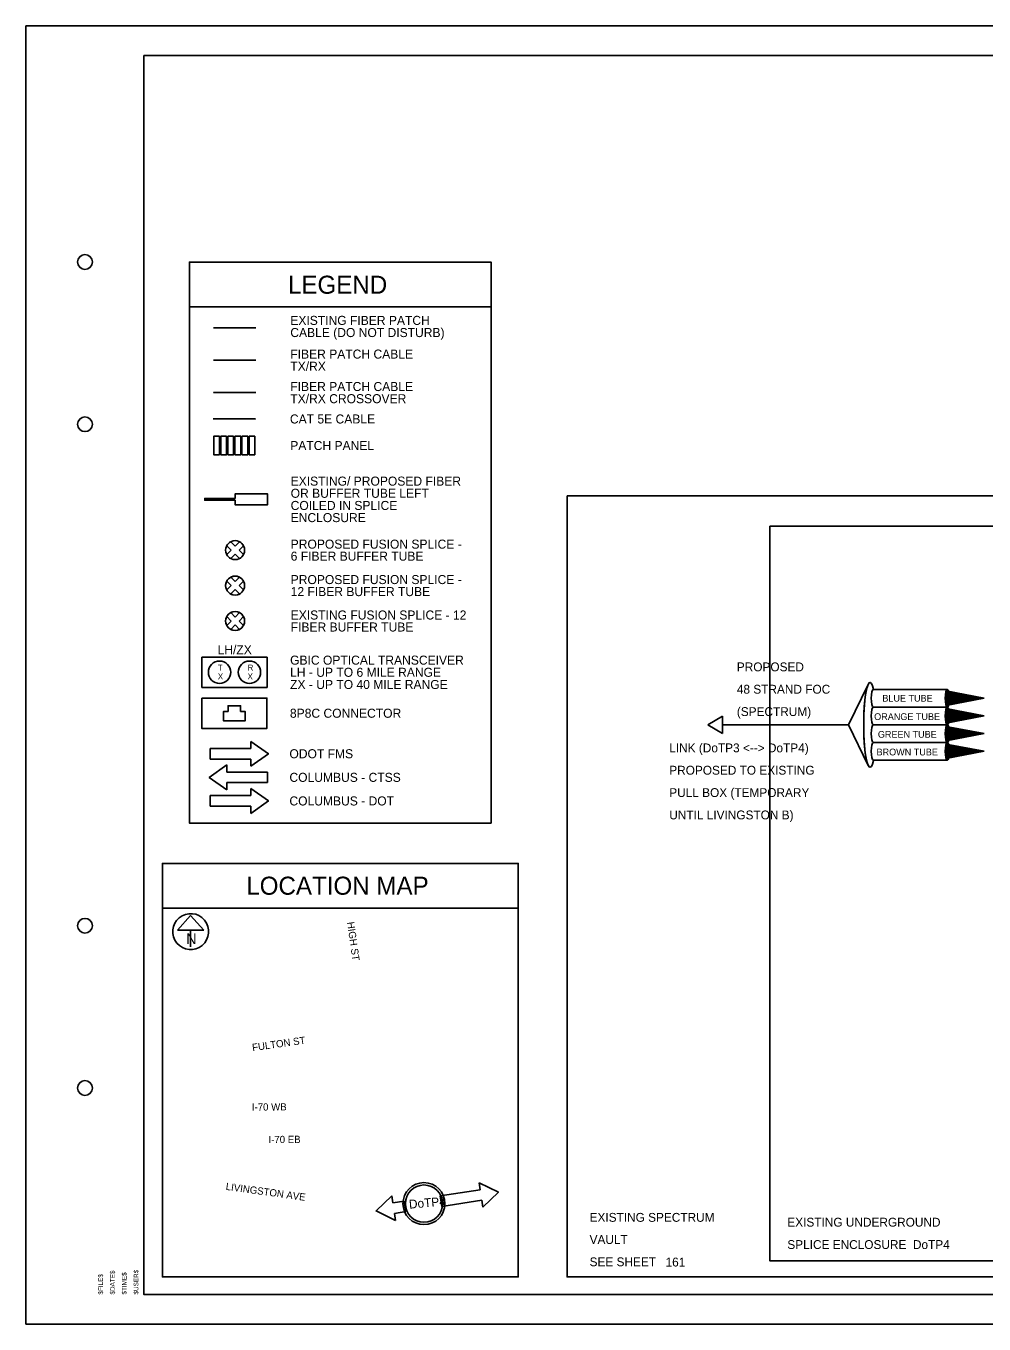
# Model space of a CAD drawing. Extents: x 1805893 to 1833564, y 708898 to 716199.
# Drawn here: x 1832883.8 to 1833208.6, y 714257.9 to 714697.9 of the extents above; entities that cross this region are included whole.
import ezdxf

# ---------------------------------------------------------------- set-up
doc = ezdxf.new("R2010")
doc.units = 0
for name, color, linetype in [('BR_P_Sub_Hidden', 7, 'Continuous'), ('BR_X_Slab_Object', 7, 'Continuous'), ('SH_Border', 7, 'Continuous'), ('SH_Cut_Line', 7, 'Continuous'), ('SH_Data', 7, 'Continuous'), ('SH_Text', 7, 'Continuous'), ('UT_X_Misc_Cells', 7, 'Continuous')]:
    doc.layers.add(name, color=color, linetype=linetype)

msp = doc.modelspace()

# ---------------------------------------------------------------- linework, layer by layer
at = {"layer": 'BR_P_Sub_Hidden'}
for points in [[(1833067.2, 714538.6), (1833508.62, 714538.6), (1833508.62, 714273.91), (1833067.2, 714273.91)], [(1833135.95, 714528.32), (1833459.05, 714528.32), (1833459.05, 714279.3), (1833135.95, 714279.3)]]:
    msp.add_lwpolyline(points, close=True, dxfattribs=at)
at = {"layer": 'SH_Border'}
msp.add_lwpolyline([(1832923.78, 714687.91), (1833553.78, 714687.91), (1833553.78, 714267.91), (1832923.78, 714267.91)], close=True, dxfattribs=at)
for centre in [(1832903.78, 714617.91), (1832903.78, 714562.91), (1832903.78, 714392.91), (1832903.78, 714337.91)]:
    msp.add_circle(centre, 2.5, dxfattribs=at)
at = {"layer": 'SH_Cut_Line'}
msp.add_lwpolyline([(1832883.78, 714257.91), (1833563.78, 714257.91), (1833563.78, 714697.91), (1832883.78, 714697.91)], close=True, dxfattribs=at)
at = {"layer": 'SH_Data'}
for p, q in [((1832947.38, 714595.63), (1832961.72, 714595.63)), ((1832947.38, 714584.63), (1832961.72, 714584.63)), ((1832953.32, 714520.23), (1832951.83, 714521.72)), ((1832951.83, 714521.72), (1832953.32, 714520.23)), ((1832954.68, 714521.58), (1832953.19, 714523.08)), ((1832954.68, 714521.58), (1832953.19, 714523.08)), ((1832954.68, 714521.58), (1832956.17, 714523.08)), ((1832956.17, 714523.08), (1832954.68, 714521.58)), ((1832956.03, 714520.23), (1832957.53, 714521.72)), ((1832956.03, 714520.23), (1832957.53, 714521.72)), ((1832951.83, 714518.74), (1832953.32, 714520.23)), ((1832953.32, 714520.23), (1832951.83, 714518.74)), ((1832953.19, 714517.38), (1832954.68, 714518.87)), ((1832953.19, 714517.38), (1832954.68, 714518.87)), ((1832956.17, 714517.38), (1832954.68, 714518.87)), ((1832954.68, 714518.87), (1832956.17, 714517.38)), ((1832957.53, 714518.74), (1832956.03, 714520.23)), ((1832957.53, 714518.74), (1832956.03, 714520.23)), ((1832953.32, 714508.22), (1832951.83, 714509.71)), ((1832953.32, 714508.22), (1832951.83, 714509.71)), ((1832951.83, 714506.73), (1832953.32, 714508.22)), ((1832951.83, 714506.73), (1832953.32, 714508.22)), ((1832954.68, 714509.57), (1832953.19, 714511.07)), ((1832953.19, 714511.07), (1832954.68, 714509.57)), ((1832954.68, 714509.57), (1832956.17, 714511.07)), ((1832954.68, 714509.57), (1832956.17, 714511.07)), ((1832956.03, 714508.22), (1832957.53, 714509.71)), ((1832957.53, 714509.71), (1832956.03, 714508.22)), ((1832957.53, 714506.73), (1832956.03, 714508.22)), ((1832956.03, 714508.22), (1832957.53, 714506.73)), ((1832953.19, 714505.37), (1832954.68, 714506.86)), ((1832954.68, 714506.86), (1832953.19, 714505.37)), ((1832956.17, 714505.37), (1832954.68, 714506.86)), ((1832956.17, 714505.37), (1832954.68, 714506.86)), ((1832954.68, 714497.57), (1832953.19, 714499.06)), ((1832953.19, 714499.06), (1832954.68, 714497.57)), ((1832954.68, 714497.57), (1832956.17, 714499.06)), ((1832954.68, 714497.57), (1832956.17, 714499.06)), ((1832953.32, 714496.21), (1832951.83, 714497.71)), ((1832953.32, 714496.21), (1832951.83, 714497.71)), ((1832951.83, 714494.72), (1832953.32, 714496.21)), ((1832951.83, 714494.72), (1832953.32, 714496.21)), ((1832953.19, 714493.37), (1832954.68, 714494.86)), ((1832954.68, 714494.86), (1832953.19, 714493.37)), ((1832956.17, 714493.37), (1832954.68, 714494.86)), ((1832956.17, 714493.37), (1832954.68, 714494.86)), ((1832956.03, 714496.21), (1832957.53, 714497.71)), ((1832957.53, 714497.71), (1832956.03, 714496.21)), ((1832957.53, 714494.72), (1832956.03, 714496.21)), ((1832956.03, 714496.21), (1832957.53, 714494.72)), ((1833171.08, 714473.04), (1833196.13, 714473.04)), ((1833171.08, 714473.04), (1833196.13, 714473.04)), ((1833208.55, 714470.04), (1833195.58, 714472.06)), ((1833208.55, 714470.04), (1833195.71, 714472.51)), ((1833208.55, 714470.04), (1833195.38, 714470.26)), ((1833208.55, 714470.04), (1833195.38, 714469.81)), ((1833208.55, 714470.04), (1833195.4, 714470.71)), ((1833208.55, 714470.04), (1833195.4, 714469.36)), ((1833208.55, 714470.04), (1833195.44, 714471.16)), ((1833208.55, 714470.04), (1833195.44, 714468.91)), ((1833208.55, 714470.04), (1833195.49, 714471.61)), ((1833208.55, 714470.04), (1833195.49, 714468.46)), ((1833208.55, 714470.04), (1833195.58, 714468.01)), ((1833208.55, 714470.04), (1833195.71, 714467.56)), ((1833119.93, 714463.9), (1833114.91, 714461)), ((1833119.93, 714458.1), (1833119.93, 714463.9)), ((1833196.13, 714467.04), (1833171.08, 714467.04)), ((1833171.08, 714467.04), (1833196.13, 714467.04)), ((1833208.55, 714464.04), (1833195.38, 714464.26)), ((1833208.55, 714464.04), (1833195.38, 714463.81)), ((1833208.55, 714464.04), (1833195.4, 714464.71)), ((1833208.55, 714464.04), (1833195.4, 714463.36)), ((1833208.55, 714464.04), (1833195.44, 714465.16)), ((1833208.55, 714464.04), (1833195.44, 714462.91)), ((1833208.55, 714464.04), (1833195.49, 714465.61)), ((1833208.55, 714464.04), (1833195.49, 714462.46)), ((1833208.55, 714464.04), (1833195.58, 714466.06)), ((1833208.55, 714464.04), (1833195.58, 714462.01)), ((1833208.55, 714464.04), (1833195.71, 714466.51)), ((1833208.55, 714464.04), (1833195.71, 714461.56)), ((1833114.91, 714461), (1833119.93, 714458.1)), ((1833162.66, 714461), (1833119.93, 714461)), ((1833171.08, 714461.04), (1833196.13, 714461.04)), ((1833196.13, 714461.04), (1833171.08, 714461.04)), ((1833208.55, 714458.04), (1833195.44, 714459.16)), ((1833208.55, 714458.04), (1833195.49, 714459.61)), ((1833208.55, 714458.04), (1833195.58, 714460.06)), ((1833208.55, 714458.04), (1833195.71, 714460.51)), ((1832959.96, 714453.02), (1832959.96, 714455.42)), ((1833196.13, 714455.04), (1833171.08, 714455.04)), ((1833171.08, 714455.04), (1833196.13, 714455.04)), ((1833208.55, 714458.04), (1833195.38, 714458.26)), ((1833208.55, 714458.04), (1833195.38, 714457.81)), ((1833208.55, 714458.04), (1833195.4, 714458.71)), ((1833208.55, 714458.04), (1833195.4, 714457.36)), ((1833208.55, 714458.04), (1833195.44, 714456.91)), ((1833208.55, 714458.04), (1833195.49, 714456.46)), ((1833208.55, 714458.04), (1833195.58, 714456.01)), ((1833208.55, 714458.04), (1833195.71, 714455.56)), ((1833208.55, 714452.04), (1833195.71, 714454.51)), ((1832946.22, 714453.02), (1832959.96, 714453.02)), ((1832946.22, 714449.42), (1832946.22, 714453.02)), ((1833208.55, 714452.04), (1833195.38, 714452.26)), ((1833208.55, 714452.04), (1833195.38, 714451.81)), ((1833208.55, 714452.04), (1833195.4, 714452.71)), ((1833208.55, 714452.04), (1833195.4, 714451.36)), ((1833208.55, 714452.04), (1833195.44, 714453.16)), ((1833208.55, 714452.04), (1833195.44, 714450.91)), ((1833208.55, 714452.04), (1833195.49, 714453.61)), ((1833208.55, 714452.04), (1833195.49, 714450.46)), ((1833208.55, 714452.04), (1833195.58, 714454.06)), ((1833208.55, 714452.04), (1833195.58, 714450.01)), ((1833208.55, 714452.04), (1833195.71, 714449.56)), ((1832959.96, 714449.42), (1832946.22, 714449.42)), ((1832951.89, 714447.42), (1832951.89, 714445.02)), ((1832959.96, 714447.02), (1832959.96, 714449.42)), ((1833196.13, 714449.04), (1833171.08, 714449.04)), ((1832951.89, 714445.02), (1832965.62, 714445.02)), ((1832965.62, 714441.42), (1832951.89, 714441.42)), ((1832951.89, 714441.42), (1832951.89, 714439.02)), ((1832965.62, 714445.02), (1832965.62, 714441.42)), ((1832946.22, 714437.02), (1832959.96, 714437.02)), ((1832946.22, 714433.42), (1832946.22, 714437.02)), ((1832959.96, 714437.02), (1832959.96, 714439.42)), ((1832959.96, 714433.42), (1832946.22, 714433.42)), ((1832959.96, 714431.02), (1832959.96, 714433.42))]:
    msp.add_line(p, q, dxfattribs=at)
for points in [[(1832939.21, 714617.86), (1833041.44, 714617.86), (1833041.44, 714602.75), (1832939.21, 714602.75)], [(1833041.44, 714617.86), (1833041.44, 714427.7), (1832939.21, 714427.7), (1832939.21, 714617.86)], [(1832949.38, 714558.81), (1832949.38, 714552.56), (1832947.42, 714552.56), (1832947.42, 714558.81)], [(1832951.78, 714558.81), (1832951.78, 714552.56), (1832949.82, 714552.56), (1832949.82, 714558.81)], [(1832954.18, 714558.81), (1832954.18, 714552.56), (1832952.21, 714552.56), (1832952.21, 714558.81)], [(1832956.57, 714558.81), (1832956.57, 714552.56), (1832954.61, 714552.56), (1832954.61, 714558.81)], [(1832958.97, 714558.81), (1832958.97, 714552.56), (1832957, 714552.56), (1832957, 714558.81)], [(1832961.36, 714558.81), (1832961.36, 714552.56), (1832959.4, 714552.56), (1832959.4, 714558.81)], [(1832943.42, 714483.95), (1832965.52, 714483.95), (1832965.52, 714473.7), (1832943.42, 714473.7)], [(1832943.37, 714470.07), (1832965.46, 714470.07), (1832965.46, 714459.82), (1832943.37, 714459.82)], [(1833050.65, 714414.04), (1832930.01, 714414.04), (1832930.01, 714398.93), (1833050.65, 714398.93)], [(1833050.65, 714398.93), (1832930.01, 714398.93), (1832930.01, 714414.04), (1833050.65, 714414.04)], [(1833050.65, 714398.93), (1833050.65, 714273.91), (1832930.01, 714273.91), (1832930.01, 714398.93)], [(1833050.65, 714398.93), (1833050.65, 714273.91), (1832930.01, 714273.91), (1832930.01, 714398.93)], [(1833050.65, 714398.93), (1833050.65, 714273.91), (1832930.01, 714273.91), (1832930.01, 714398.93)], [(1833050.65, 714398.93), (1833050.65, 714273.91), (1832930.01, 714273.91), (1832930.01, 714398.93)]]:
    msp.add_lwpolyline(points, close=True, dxfattribs=at)
for points in [[(1832961.75, 714573.63), (1832947.38, 714573.63), (1832947.38, 714573.63), (1832947.38, 714573.63)], [(1832947.24, 714564.69), (1832961.58, 714564.72), (1832961.58, 714564.72)], [(1832944.38, 714537.75), (1832944.38, 714537.45), (1832944.38, 714537.14), (1832954.67, 714537.14), (1832954.67, 714535.61), (1832965.71, 714535.61), (1832965.71, 714539.28), (1832954.67, 714539.28), (1832954.67, 714537.75), (1832944.38, 714537.75)], [(1832965.71, 714535.61), (1832965.71, 714539.28), (1832954.67, 714539.28), (1832954.67, 714537.75), (1832944.38, 714537.75), (1832944.38, 714537.45), (1832944.38, 714537.14), (1832954.67, 714537.14), (1832954.67, 714535.61), (1832965.71, 714535.61)], [(1833169.26, 714474.74), (1833162.66, 714461), (1833169.26, 714447.26)], [(1833169.26, 714474.74), (1833162.66, 714461), (1833169.26, 714447.26)], [(1832956.54, 714465.55), (1832958.05, 714465.55), (1832958.05, 714462.32), (1832950.78, 714462.32), (1832950.78, 714465.55), (1832952.29, 714465.55)], [(1832952.29, 714465.55), (1832952.29, 714467.46), (1832956.54, 714467.46), (1832956.54, 714465.55)], [(1832959.96, 714455.42), (1832965.96, 714451.22), (1832959.96, 714447.02)], [(1832951.89, 714439.02), (1832945.89, 714443.22), (1832951.89, 714447.42)], [(1832959.96, 714439.42), (1832965.96, 714435.22), (1832959.96, 714431.02)]]:
    msp.add_lwpolyline(points, dxfattribs=at)
for centre, radius in [((1832954.68, 714520.23), 3.22), ((1832954.68, 714508.22), 3.22), ((1832954.68, 714496.21), 3.22), ((1832949.42, 714478.83), 3.81), ((1832959.52, 714478.83), 3.81)]:
    msp.add_circle(centre, radius, dxfattribs=at)
for centre, start, end in [((1832954.68, 714520.23), 117.647, 152.353), ((1832954.68, 714520.23), 27.647, 62.353), ((1832954.68, 714520.23), 207.647, 242.353), ((1832954.68, 714520.23), 297.647, 332.353), ((1832954.68, 714508.22), 152.353, 207.647), ((1832954.68, 714508.22), 62.353, 117.647), ((1832954.68, 714508.22), 332.353, 27.647), ((1832954.68, 714508.22), 242.353, 297.647), ((1832954.68, 714496.21), 62.353, 117.647), ((1832954.68, 714496.21), 152.353, 207.647), ((1832954.68, 714496.21), 332.353, 27.647), ((1832954.68, 714496.21), 242.353, 297.647)]:
    msp.add_arc(centre, 3.22, start, end, dxfattribs=at)
for centre, major_axis, ratio, start_param, end_param in [((1833169.9, 714461), (0, -14.39), 0.149566, 2.561295, 6.863483), ((1833169.9, 714461), (0, -14.39), 0.149566, 2.561295, 6.863483), ((1833169.9, 714461), (0, -14.39), 0.149566, 3.443628, 5.98115), ((1833171.08, 714470.04), (0, -3), 0.25, 3.141593, 6.283185), ((1833171.08, 714470.04), (0, -3), 0.25, 3.141593, 6.283185), ((1833171.08, 714470.04), (0, -3), 0.25, 3.141593, 6.283185), ((1833196.13, 714470.04), (0, -3), 0.25, 3.141593, 6.283185), ((1833171.08, 714464.04), (0, -3), 0.25, 3.141593, 6.283185), ((1833171.08, 714464.04), (0, -3), 0.25, 3.141593, 6.283185), ((1833171.08, 714464.04), (0, -3), 0.25, 3.141593, 6.283185), ((1833196.13, 714464.04), (0, -3), 0.25, 3.141593, 6.283185), ((1833171.08, 714458.04), (0, -3), 0.25, 3.141593, 6.283185), ((1833171.08, 714458.04), (0, -3), 0.25, 3.141593, 6.283185), ((1833171.08, 714458.04), (0, -3), 0.25, 3.141593, 6.283185), ((1833196.13, 714458.04), (0, -3), 0.25, 3.141593, 6.283185), ((1833171.08, 714452.04), (0, -3), 0.25, 3.141593, 6.283185), ((1833171.08, 714452.04), (0, -3), 0.25, 3.141593, 6.283185), ((1833171.08, 714452.04), (0, -3), 0.25, 3.141593, 6.283185), ((1833196.13, 714452.04), (0, -3), 0.25, 3.141593, 6.283185)]:
    msp.add_ellipse(centre, major_axis=major_axis, ratio=ratio, start_param=start_param, end_param=end_param, dxfattribs=at)
for centre in [(1833196.13, 714470.04), (1833196.13, 714464.04), (1833196.13, 714458.04), (1833196.13, 714452.04)]:
    msp.add_ellipse(centre, major_axis=(0, -3), ratio=0.25, dxfattribs=at)
at = {"layer": 'SH_Text'}
for p, q in [((1832939.61, 714396.42), (1832935.11, 714391.42)), ((1832944.12, 714391.42), (1832939.61, 714396.42)), ((1832935.11, 714391.42), (1832944.12, 714391.42)), ((1832939.61, 714391.42), (1832939.61, 714385.76)), ((1833037.72, 714303.43), (1833037.36, 714305.8)), ((1833007.76, 714301.34), (1833008.14, 714298.97)), ((1833024.15, 714301.33), (1833037.72, 714303.43)), ((1833024.7, 714297.77), (1833024.15, 714301.33)), ((1833008.14, 714298.97), (1833012.01, 714299.59)), ((1833012.57, 714296.03), (1833008.7, 714295.42)), ((1833012.01, 714299.59), (1833012.57, 714296.03)), ((1833038.28, 714299.87), (1833024.7, 714297.77)), ((1833038.64, 714297.5), (1833038.28, 714299.87)), ((1833008.7, 714295.42), (1833009.07, 714293.05))]:
    msp.add_line(p, q, dxfattribs=at)
for points in [[(1833037.36, 714305.8), (1833043.93, 714302.57), (1833038.64, 714297.5)], [(1833009.07, 714293.05), (1833002.49, 714296.26), (1833007.76, 714301.34)]]:
    msp.add_lwpolyline(points, dxfattribs=at)
for radius in [7.11, 6.31]:
    msp.add_circle((1833018.69, 714298.73), radius, dxfattribs=at)
msp.add_arc((1832939.61, 714390.95), 6.08, 129.7798, 129.7633, dxfattribs=at)

# ---------------------------------------------------------------- texts
at = {"layer": 'BR_X_Slab_Object'}
for s, p in [('T', (1832948.82, 714479.43)), ('R', (1832958.91, 714479.43)), ('X', (1832948.82, 714476.43)), ('X', (1832958.91, 714476.43))]:
    msp.add_text(s, height=2, rotation=0.0475, dxfattribs=at).set_placement(p)
msp.add_text('161', height=3, dxfattribs=at).set_placement((1833100.6, 714277.41))
at = {"layer": 'SH_Data'}
for s, height, p in [('LEGEND', 6.119, (1832972.59, 714607.14)), ('EXISTING FIBER PATCH ', 3.0596, (1832973.39, 714596.58)), ('CABLE (DO NOT DISTURB)', 3.0596, (1832973.39, 714592.46)), ('FIBER PATCH CABLE', 3.0596, (1832973.39, 714585.16)), ('TX/RX', 3.06, (1832973.39, 714581.04)), ('TX/RX CROSSOVER', 3.0596, (1832973.39, 714570.04)), ('FIBER PATCH CABLE', 3.0596, (1832973.39, 714574.16)), ('CAT 5E CABLE', 3.0596, (1832973.26, 714563.16)), ('PATCH PANEL', 3.0596, (1832973.37, 714554.16)), ('EXISTING/ PROPOSED FIBER ', 3.0596, (1832973.51, 714542.1)), ('OR BUFFER TUBE LEFT ', 3.0596, (1832973.51, 714537.98)), ('COILED IN SPLICE ', 3.0596, (1832973.51, 714533.85)), ('ENCLOSURE', 3.06, (1832973.51, 714529.73)), ('PROPOSED FUSION SPLICE - ', 3.0596, (1832973.52, 714520.74)), ('6 FIBER BUFFER TUBE', 3.0596, (1832973.52, 714516.66)), ('PROPOSED FUSION SPLICE - ', 3.0596, (1832973.52, 714508.73)), ('12 FIBER BUFFER TUBE', 3.0596, (1832973.52, 714504.65)), ('EXISTING FUSION SPLICE - 12 ', 3.0596, (1832973.52, 714496.72)), ('FIBER BUFFER TUBE', 3.0596, (1832973.52, 714492.65)), ('LH/ZX', 3.06, (1832948.74, 714484.95)), ('GBIC OPTICAL TRANSCEIVER', 3.0596, (1832973.32, 714481.42)), ('LH - UP TO 6 MILE RANGE', 3.0596, (1832973.32, 714477.3)), ('ZX - UP TO 40 MILE RANGE', 3.0596, (1832973.32, 714473.17)), ('BLUE TUBE', 2.295, (1833174.08, 714468.89)), ('8P8C CONNECTOR', 3.0596, (1832973.26, 714463.42)), ('ORANGE TUBE', 2.2947, (1833171.31, 714462.65)), ('GREEN TUBE', 2.295, (1833172.56, 714456.65)), ('LINK (DoTP3 <--> DoTP4)', 3, (1833101.85, 714451.7)), ('ODOT FMS', 3.06, (1832973.09, 714449.69)), ('BROWN TUBE', 2.295, (1833172.12, 714450.65)), ('PROPOSED TO EXISTING ', 3, (1833101.85, 714444.13)), ('COLUMBUS - CTSS', 3.0596, (1832973.09, 714441.69)), ('PULL BOX (TEMPORARY', 3, (1833101.85, 714436.55)), ('COLUMBUS - DOT', 3.0596, (1832973.09, 714433.69)), ('UNTIL LIVINGSTON B)', 3, (1833101.85, 714428.97)), ('LOCATION MAP', 6.1191, (1832958.46, 714403.43)), ('EXISTING SPECTRUM', 3, (1833074.84, 714292.57)), ('EXISTING UNDERGROUND ', 3, (1833141.87, 714290.93)), ('VAULT', 3, (1833074.84, 714285.04)), ('SPLICE ENCLOSURE  DoTP4', 3, (1833141.87, 714283.35)), ('SEE SHEET', 3, (1833074.84, 714277.49))]:
    msp.add_text(s, height=height, dxfattribs=at).set_placement(p)
for s, p in [('PROPOSED', (1833124.76, 714479.16)), ('48 STRAND FOC', (1833124.76, 714471.58)), ('(SPECTRUM)', (1833124.76, 714464))]:
    msp.add_text(s, height=3, rotation=360, dxfattribs=at).set_placement(p)
at = {"layer": 'SH_Text'}
for s, height, rotation, p in [('HIGH ST', 2.448, 278.061, (1832992.62, 714394.08)), ('N', 3.66, 360, (1832938.09, 714386.68)), ('FULTON ST', 2.448, 8.061, (1832960.62, 714350.41)), ('I-70 WB', 2.448, 0.3445, (1832960.34, 714330.24)), ('I-70 EB', 2.448, 0.3445, (1832965.98, 714319.23)), ('LIVINGSTON AVE', 2.4477, 352.086, (1832951.39, 714303.41)), ('DoTP4', 3, 5, (1833013.74, 714297))]:
    msp.add_text(s, height=height, rotation=rotation, dxfattribs=at).set_placement(p)
at = {"layer": 'UT_X_Misc_Cells'}
for s, p in [('$FILE$', (1832909.87, 714267.91)), ('$DATE$', (1832913.87, 714267.91)), ('$TIME$', (1832917.87, 714267.91)), ('$USER$', (1832921.87, 714267.91))]:
    msp.add_text(s, height=1.56, rotation=90, dxfattribs=at).set_placement(p)

doc.saveas('drawing.dxf')
